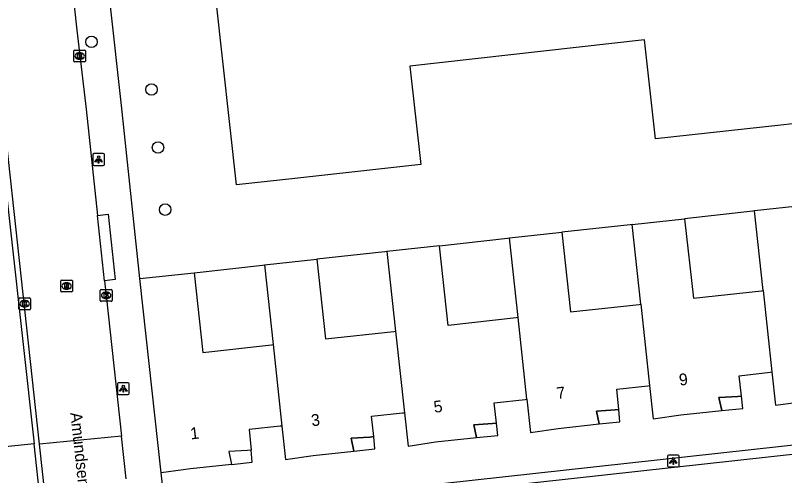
# Model space of a CAD drawing. Extents: x 161253 to 161848, y 384872 to 385383.
# Drawn here: x 161329 to 161394.3, y 385161 to 385200.1 of the extents above; entities that cross this region are included whole.
import ezdxf

# ---------------------------------------------------------------- set-up
doc = ezdxf.new("R2010")
doc.units = 0
for name, color, linetype in [('IMGEO_Boom', 7, 'Continuous'), ('IMGEO_Erf', 7, 'Continuous'), ('IMGEO_Kolk', 7, 'Continuous'), ('IMGEO_Lichtpunt', 7, 'Continuous'), ('IMGEO_Openbare_ruimte_label', 7, 'Continuous'), ('IMGEO_Pand', 7, 'Continuous'), ('IMGEO_Pand_nummerreeks', 7, 'Continuous'), ('IMGEO_Pand_overbouw', 7, 'Continuous'), ('IMGEO_Rijbaan_lokaal_open', 7, 'Continuous'), ('IMGEO_Rioolput', 7, 'Continuous'), ('IMGEO_Voetpad_open', 7, 'Continuous')]:
    doc.layers.add(name, color=color, linetype=linetype)

msp = doc.modelspace()

# ---------------------------------------------------------------- linework, layer by layer
at = {"layer": 'IMGEO_Boom'}
for centre in [(161335.451, 385197.848), (161340.545, 385193.807), (161341.095, 385188.878), (161341.701, 385183.61)]:
    msp.add_circle(centre, 0.489, dxfattribs=at)
at = {"layer": 'IMGEO_Erf'}
for points in [[(161391.744, 385183.5), (161391.585, 385183.483), (161385.798, 385182.842)], [(161381.35, 385182.348), (161381.191, 385182.33), (161375.383, 385181.692)], [(161364.985, 385180.545), (161370.771, 385181.192), (161370.93, 385181.209)], [(161360.525, 385180.056), (161360.366, 385180.039), (161354.573, 385179.402)], [(161344.167, 385178.254), (161349.972, 385178.893), (161350.131, 385178.911)]]:
    msp.add_lwpolyline(points, dxfattribs=at)
at = {"layer": 'IMGEO_Kolk'}
for p, q in [((161333.937, 385196.219), (161333.937, 385197.071)), ((161334.012, 385197.145), (161334.864, 385197.145)), ((161334.425, 385196.925), (161334.45, 385196.925)), ((161334.938, 385197.071), (161334.938, 385196.219)), ((161334.448, 385196.365), (161334.423, 385196.365)), ((161334.864, 385196.145), (161334.012, 385196.145)), ((161336.192, 385175.901), (161336.192, 385176.753)), ((161336.267, 385176.827), (161337.119, 385176.827)), ((161336.68, 385176.607), (161336.705, 385176.607)), ((161337.193, 385176.753), (161337.193, 385175.901)), ((161329.269, 385175.193), (161329.269, 385176.045)), ((161329.344, 385176.119), (161330.196, 385176.119)), ((161330.27, 385176.045), (161330.27, 385175.193)), ((161336.703, 385176.047), (161336.678, 385176.047)), ((161329.78, 385175.339), (161329.755, 385175.339)), ((161329.757, 385175.899), (161329.782, 385175.899)), ((161337.119, 385175.827), (161336.267, 385175.827)), ((161330.196, 385175.119), (161329.344, 385175.119))]:
    msp.add_line(p, q, dxfattribs=at)
for points in [[(161333.937, 385196.219), (161333.937, 385197.071)], [(161334.012, 385197.145), (161334.864, 385197.145)], [(161334.258, 385196.845), (161334.381, 385196.845), (161334.381, 385196.694), (161334.511, 385196.845), (161334.675, 385196.845), (161334.529, 385196.694), (161334.682, 385196.445), (161334.53, 385196.445), (161334.445, 385196.609), (161334.381, 385196.542), (161334.381, 385196.445), (161334.258, 385196.445), (161334.258, 385196.845)], [(161334.938, 385197.071), (161334.938, 385196.219)], [(161334.864, 385196.145), (161334.012, 385196.145)], [(161336.192, 385175.901), (161336.192, 385176.753)], [(161336.267, 385176.827), (161337.119, 385176.827)], [(161337.193, 385176.753), (161337.193, 385175.901)], [(161329.269, 385175.193), (161329.269, 385176.045)], [(161329.344, 385176.119), (161330.196, 385176.119)], [(161330.27, 385176.045), (161330.27, 385175.193)], [(161336.513, 385176.527), (161336.636, 385176.527), (161336.636, 385176.376), (161336.766, 385176.527), (161336.93, 385176.527), (161336.784, 385176.376), (161336.937, 385176.127), (161336.785, 385176.127), (161336.7, 385176.291), (161336.636, 385176.224), (161336.636, 385176.127), (161336.513, 385176.127), (161336.513, 385176.527)], [(161329.59, 385175.819), (161329.713, 385175.819), (161329.713, 385175.668), (161329.843, 385175.819), (161330.007, 385175.819), (161329.861, 385175.668), (161330.014, 385175.419), (161329.862, 385175.419), (161329.777, 385175.583), (161329.713, 385175.516), (161329.713, 385175.419), (161329.59, 385175.419), (161329.59, 385175.819)], [(161337.119, 385175.827), (161336.267, 385175.827)], [(161330.196, 385175.119), (161329.344, 385175.119)]]:
    msp.add_lwpolyline(points, dxfattribs=at)
for centre, start, end in [((161334.014, 385197.069), 91.55205, 178.44795), ((161334.014, 385197.069), 91.55205, 178.44795), ((161334.862, 385197.069), 1.55205, 88.44795), ((161334.862, 385197.069), 1.55205, 88.44795), ((161334.014, 385196.221), 181.55205, 268.44795), ((161334.014, 385196.221), 181.55205, 268.44795), ((161334.862, 385196.221), 271.55205, 358.44795), ((161334.862, 385196.221), 271.55205, 358.44795), ((161336.269, 385176.751), 91.55205, 178.44795), ((161336.269, 385176.751), 91.55205, 178.44795), ((161337.117, 385176.751), 1.55205, 88.44795), ((161337.117, 385176.751), 1.55205, 88.44795), ((161329.346, 385176.043), 91.55205, 178.44795), ((161329.346, 385176.043), 91.55205, 178.44795), ((161330.194, 385176.043), 1.55205, 88.44795), ((161330.194, 385176.043), 1.55205, 88.44795), ((161336.269, 385175.903), 181.55205, 268.44795), ((161336.269, 385175.903), 181.55205, 268.44795), ((161337.117, 385175.903), 271.55205, 358.44795), ((161337.117, 385175.903), 271.55205, 358.44795), ((161329.346, 385175.195), 181.55205, 268.44795), ((161329.346, 385175.195), 181.55205, 268.44795), ((161330.194, 385175.195), 271.55205, 358.44795), ((161330.194, 385175.195), 271.55205, 358.44795)]:
    msp.add_arc(centre, 0.0765, start, end, dxfattribs=at)
for centre, major_axis, ratio, start_param, end_param in [((161334.424, 385196.645), (-0.387, 0.002), 0.722429, 4.712389, 7.853982), ((161334.449, 385196.645), (-0.39, 0.002), 0.717154, 1.570796, 4.712389), ((161336.679, 385176.327), (-0.387, 0.002), 0.722429, 4.712389, 7.853982), ((161336.704, 385176.327), (-0.39, 0.002), 0.717154, 1.570796, 4.712389), ((161329.756, 385175.619), (-0.387, 0.002), 0.722429, 4.712389, 7.853982), ((161329.781, 385175.619), (-0.39, 0.002), 0.717154, 1.570796, 4.712389)]:
    msp.add_ellipse(centre, major_axis=major_axis, ratio=ratio, start_param=start_param, end_param=end_param, dxfattribs=at)
at = {"layer": 'IMGEO_Lichtpunt'}
for p, q in [((161336.451, 385188.361), (161335.643, 385188.361)), ((161336.451, 385188.361), (161335.643, 385188.361)), ((161335.549, 385188.266), (161335.549, 385187.459)), ((161335.549, 385188.266), (161335.549, 385187.459)), ((161336.545, 385187.459), (161336.545, 385188.266)), ((161336.545, 385187.459), (161336.545, 385188.266)), ((161335.643, 385187.365), (161336.451, 385187.365)), ((161335.643, 385187.365), (161336.451, 385187.365)), ((161337.651, 385168.815), (161337.651, 385168.008)), ((161337.651, 385168.815), (161337.651, 385168.008)), ((161338.553, 385168.91), (161337.745, 385168.91)), ((161338.553, 385168.91), (161337.745, 385168.91)), ((161338.647, 385168.008), (161338.647, 385168.815)), ((161338.647, 385168.008), (161338.647, 385168.815)), ((161337.745, 385167.914), (161338.553, 385167.914)), ((161337.745, 385167.914), (161338.553, 385167.914)), ((161384.344, 385162.68), (161384.344, 385161.873)), ((161384.344, 385162.68), (161384.344, 385161.873)), ((161385.246, 385162.775), (161384.438, 385162.775)), ((161385.246, 385162.775), (161384.438, 385162.775)), ((161385.34, 385161.873), (161385.34, 385162.68)), ((161385.34, 385161.873), (161385.34, 385162.68)), ((161384.438, 385161.779), (161385.246, 385161.779)), ((161384.438, 385161.779), (161385.246, 385161.779))]:
    msp.add_line(p, q, dxfattribs=at)
for points in [[(161335.923, 385187.93), (161335.962, 385187.902), (161335.774, 385187.64), (161335.736, 385187.667), (161335.923, 385187.93)], [(161336.025, 385187.882), (161336.072, 385187.882), (161336.072, 385187.56), (161336.025, 385187.56), (161336.025, 385187.882)], [(161336.135, 385187.902), (161336.173, 385187.929), (161336.36, 385187.667), (161336.321, 385187.639), (161336.135, 385187.902)], [(161338.025, 385168.479), (161338.064, 385168.451), (161337.876, 385168.189), (161337.838, 385168.216), (161338.025, 385168.479)], [(161338.127, 385168.431), (161338.174, 385168.431), (161338.174, 385168.109), (161338.127, 385168.109), (161338.127, 385168.431)], [(161338.237, 385168.451), (161338.275, 385168.478), (161338.462, 385168.216), (161338.423, 385168.188), (161338.237, 385168.451)], [(161384.718, 385162.344), (161384.757, 385162.316), (161384.569, 385162.054), (161384.531, 385162.081), (161384.718, 385162.344)], [(161384.82, 385162.296), (161384.867, 385162.296), (161384.867, 385161.974), (161384.82, 385161.974), (161384.82, 385162.296)], [(161384.93, 385162.316), (161384.968, 385162.343), (161385.155, 385162.081), (161385.116, 385162.053), (161384.93, 385162.316)]]:
    msp.add_lwpolyline(points, dxfattribs=at)
for centre in [(161336.048, 385188.064), (161338.15, 385168.613), (161384.843, 385162.478)]:
    msp.add_circle(centre, 0.0994, dxfattribs=at)
for centre, start, end in [((161335.643, 385188.266), 90, 180), ((161335.643, 385188.266), 90, 180), ((161336.451, 385188.266), 0, 90), ((161336.451, 385188.266), 0, 90), ((161335.643, 385187.459), 180, 270), ((161335.643, 385187.459), 180, 270), ((161336.451, 385187.459), 270, 0), ((161336.451, 385187.459), 270, 360), ((161337.745, 385168.815), 90, 180), ((161337.745, 385168.815), 90, 180), ((161338.553, 385168.815), 0, 90), ((161338.553, 385168.815), 0, 90), ((161337.745, 385168.008), 180, 270), ((161337.745, 385168.008), 180, 270), ((161338.553, 385168.008), 270, 0), ((161338.553, 385168.008), 270, 360), ((161384.438, 385162.68), 90, 180), ((161384.438, 385162.68), 90, 180), ((161385.246, 385162.68), 0, 90), ((161385.246, 385162.68), 0, 90), ((161384.438, 385161.873), 180, 270), ((161384.438, 385161.873), 180, 270), ((161385.246, 385161.873), 270, 0), ((161385.246, 385161.873), 270, 360)]:
    msp.add_arc(centre, 0.0946, start, end, dxfattribs=at)
at = {"layer": 'IMGEO_Pand'}
for points in [[(161388.88, 385230.104), (161390.824, 385212.393), (161388.827, 385212.174), (161389.489, 385206.312), (161397.217, 385207.042), (161398.94, 385191.336), (161393.97, 385190.79), (161383.334, 385189.623), (161382.412, 385198.032), (161362.486, 385195.783), (161363.403, 385187.435), (161352.721, 385186.262), (161347.75, 385185.717), (161346.037, 385201.322)], [(161396.212, 385183.986), (161391.744, 385183.5)], [(161392.474, 385176.74), (161391.744, 385183.5)], [(161381.35, 385182.348), (161385.798, 385182.842)], [(161385.798, 385182.842), (161386.549, 385176.083), (161392.321, 385176.723), (161392.474, 385176.74)], [(161382.083, 385175.588), (161381.35, 385182.348)], [(161370.93, 385181.209), (161375.383, 385181.692)], [(161371.665, 385174.45), (161370.93, 385181.209)], [(161375.383, 385181.692), (161376.116, 385174.932), (161381.942, 385175.572), (161382.083, 385175.588)], [(161364.985, 385180.545), (161360.525, 385180.056)], [(161371.665, 385174.45), (161371.504, 385174.432), (161365.726, 385173.786), (161364.985, 385180.545)], [(161360.525, 385180.056), (161361.26, 385173.296)], [(161350.131, 385178.911), (161354.573, 385179.402)], [(161354.573, 385179.402), (161355.319, 385172.643), (161361.107, 385173.279), (161361.26, 385173.296)], [(161350.131, 385178.911), (161350.865, 385172.151)], [(161339.547, 385177.756), (161344.167, 385178.254)], [(161344.167, 385178.254), (161344.896, 385171.493), (161350.717, 385172.135), (161350.865, 385172.151)], [(161341.369, 385161.26), (161339.547, 385177.756)], [(161392.474, 385176.74), (161393.22, 385169.836)], [(161382.083, 385175.588), (161382.832, 385168.686)], [(161372.418, 385167.527), (161371.665, 385174.45)], [(161361.26, 385173.296), (161362.014, 385166.369)], [(161350.865, 385172.151), (161351.615, 385165.238)], [(161393.22, 385169.836), (161393.526, 385167.003), (161395.885, 385167.336), (161399.358, 385167.712), (161399.123, 385168.803), (161400.714, 385168.901), (161401.024, 385168.918), (161400.824, 385170.684), (161403.479, 385170.951), (161403.638, 385170.967)], [(161382.832, 385168.686), (161383.139, 385165.855), (161385.488, 385166.19), (161388.965, 385166.554), (161388.71, 385167.652), (161390.314, 385167.741), (161390.627, 385167.777), (161390.435, 385169.518), (161393.061, 385169.818), (161393.22, 385169.836)], [(161372.418, 385167.527), (161372.725, 385164.709), (161375.077, 385165.037), (161378.557, 385165.42), (161378.33, 385166.504), (161379.921, 385166.605), (161380.213, 385166.637), (161380.045, 385168.365), (161382.673, 385168.668), (161382.832, 385168.686)], [(161362.014, 385166.369), (161362.321, 385163.547), (161364.663, 385163.905), (161368.132, 385164.263), (161367.904, 385165.349), (161369.507, 385165.454), (161369.827, 385165.484), (161369.629, 385167.21), (161372.259, 385167.509), (161372.418, 385167.527)], [(161351.615, 385165.238), (161351.923, 385162.397), (161354.269, 385162.742), (161357.727, 385163.12), (161357.493, 385164.211), (161359.083, 385164.293), (161359.406, 385164.345), (161359.227, 385166.073), (161361.855, 385166.352), (161362.014, 385166.369)], [(161351.615, 385165.238), (161351.456, 385165.221), (161348.823, 385164.941), (161348.996, 385163.19), (161348.696, 385163.166), (161347.1, 385163.076), (161347.342, 385161.981), (161343.854, 385161.606), (161341.369, 385161.26)]]:
    msp.add_lwpolyline(points, dxfattribs=at)
at = {"layer": 'IMGEO_Pand_overbouw'}
for points in [[(161390.627, 385167.777), (161390.314, 385167.741), (161388.71, 385167.652), (161388.965, 385166.554), (161390.741, 385166.74)], [(161380.213, 385166.637), (161379.921, 385166.605), (161378.33, 385166.504), (161378.557, 385165.42), (161380.313, 385165.613)], [(161369.827, 385165.484), (161369.507, 385165.454), (161367.904, 385165.349), (161368.132, 385164.263), (161369.946, 385164.45)], [(161359.406, 385164.345), (161359.083, 385164.293), (161357.493, 385164.211), (161357.727, 385163.12), (161359.513, 385163.315)], [(161348.996, 385163.19), (161348.696, 385163.166), (161347.1, 385163.076), (161347.342, 385161.981), (161349.097, 385162.17)]]:
    msp.add_lwpolyline(points, close=True, dxfattribs=at)
at = {"layer": 'IMGEO_Rijbaan_lokaal_open'}
for points in [[(161333.656, 385203.761), (161333.767, 385202.749), (161334.197, 385198.828), (161334.986, 385192.138), (161335.96, 385183.113)], [(161331.038, 385163.711), (161327.141, 385199.049)], [(161336.557, 385177.575), (161335.96, 385183.113)], [(161336.557, 385177.575), (161336.692, 385176.326), (161337.994, 385164.378)], [(161337.994, 385164.378), (161331.038, 385163.711)], [(161338.388, 385160.759), (161337.994, 385164.378)], [(161331.58, 385158.8), (161331.038, 385163.711)], [(161342.455, 385157.097), (161395.989, 385162.959), (161396.733, 385156.417)]]:
    msp.add_lwpolyline(points, dxfattribs=at)
at = {"layer": 'IMGEO_Rioolput'}
for p, q in [((161332.831, 385176.701), (161332.831, 385177.553)), ((161332.906, 385177.627), (161333.758, 385177.627)), ((161333.319, 385177.407), (161333.344, 385177.407)), ((161333.832, 385177.553), (161333.832, 385176.701)), ((161333.758, 385176.627), (161332.906, 385176.627)), ((161333.342, 385176.847), (161333.317, 385176.847))]:
    msp.add_line(p, q, dxfattribs=at)
for points in [[(161332.831, 385176.701), (161332.831, 385177.553)], [(161332.906, 385177.627), (161333.758, 385177.627)], [(161333.42, 385177.325), (161333.168, 385177.327), (161333.168, 385176.927)], [(161333.832, 385177.553), (161333.832, 385176.701)], [(161333.758, 385176.627), (161332.906, 385176.627)], [(161333.168, 385176.927), (161333.292, 385176.927), (161333.292, 385177.089), (161333.303, 385177.089)], [(161333.346, 385177.246), (161333.292, 385177.246), (161333.292, 385177.165)], [(161333.292, 385177.165), (161333.344, 385177.165)], [(161333.35, 385177.06), (161333.421, 385176.927), (161333.561, 385176.927), (161333.496, 385177.053)]]:
    msp.add_lwpolyline(points, dxfattribs=at)
for centre, radius, start, end in [((161332.908, 385177.551), 0.0765, 91.55205, 178.44795), ((161332.908, 385177.551), 0.0765, 91.55205, 178.44795), ((161333.419, 385177.215), 0.109, 350.36119, 89.41601), ((161333.756, 385177.551), 0.0765, 1.55205, 88.44795), ((161333.756, 385177.551), 0.0765, 1.55205, 88.44795), ((161332.908, 385176.703), 0.0765, 181.55205, 268.44795), ((161332.908, 385176.703), 0.0765, 181.55205, 268.44795), ((161333.302, 385177.036), 0.0533, 26.02933, 88.69889), ((161333.328, 385177.354), 0.19, 274.7715, 282.96867), ((161333.352, 385177.15), 0.0964, 77.00612, 93.18647), ((161333.366, 385177.207), 0.0378, 276.66336, 79.67722), ((161333.417, 385177.215), 0.112, 277.58423, 350.98172), ((161333.401, 385177), 0.108, 29.51342, 73.79051), ((161333.756, 385176.703), 0.0765, 271.55205, 358.44795), ((161333.756, 385176.703), 0.0765, 271.55205, 358.44795)]:
    msp.add_arc(centre, radius, start, end, dxfattribs=at)
for centre, major_axis, ratio, start_param, end_param in [((161333.318, 385177.127), (-0.387, 0.002), 0.722429, 4.712389, 7.853982), ((161333.343, 385177.127), (-0.39, 0.002), 0.717154, 1.570796, 4.712389)]:
    msp.add_ellipse(centre, major_axis=major_axis, ratio=ratio, start_param=start_param, end_param=end_param, dxfattribs=at)
at = {"layer": 'IMGEO_Voetpad_open'}
for points in [[(161339.547, 385177.756), (161337.996, 385192.452), (161337.042, 385201.126)], [(161327.141, 385199.049), (161326.646, 385198.993), (161330.574, 385163.733)], [(161335.96, 385183.113), (161336.864, 385183.211), (161337.461, 385177.673), (161336.557, 385177.575)], [(161414.901, 385165.791), (161341.751, 385157.774)], [(161330.574, 385163.733), (161328.129, 385163.466)], [(161331.58, 385158.8), (161331.129, 385158.749), (161330.574, 385163.733)], [(161341.751, 385157.774), (161341.369, 385161.26)]]:
    msp.add_lwpolyline(points, dxfattribs=at)

# ---------------------------------------------------------------- texts
at = {"layer": 'IMGEO_Openbare_ruimte_label'}
msp.add_text('Amundsenlaan', height=1, rotation=276.25793, dxfattribs=at).set_placement((161333.64, 385166.357))
at = {"layer": 'IMGEO_Pand_nummerreeks'}
for s, rotation, p in [('9', 6.8182, (161385.39, 385168.664)), ('7', 6.93852, (161374.992, 385167.525)), ('5', 7.00727, (161364.561, 385166.363)), ('3', 7.08749, (161354.16, 385165.216)), ('1', 6.88122, (161343.894, 385164.103))]:
    msp.add_text(s, height=1, rotation=rotation, dxfattribs=at).set_placement(p)

doc.saveas('drawing.dxf')
